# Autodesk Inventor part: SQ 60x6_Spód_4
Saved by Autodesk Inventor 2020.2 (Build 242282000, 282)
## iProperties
Created: 2006-08
Part Number: SQ 60x6_Spód_4
Material: Ogólny
Document SubType Name: Modeling
Designer: F.Stasiak
Manufacturer: Standard
Standards Organization: Custom
Stock Number: DIN EN 10210-2 SQ 60x6
Density: 1 g/cm^3
Appearance: Domyślna
Manager: www.cadconsulting.pl
Company: Fabian Stasiak CAD Consulting
G_L: 1000,0 mm
G_W: 60,000 mm
G_H: 60,000 mm
AFG_Item: 60 x 60 x 6
Author: F.Stasiak
Subject: Zbiór ćwiczeń. Autodesk Inventor 2020. Kurs podstawowy
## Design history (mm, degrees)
sketch "AFG_Detailed"
  geometry: L1 (-12, 54)-(-48, 54); L2 (-54, 48)-(-54, 12); L3 (-48, 6)-(-12, 6); L4 (-6, 12)-(-6, 48); L5 (-12, 60)-(-48, 60); L6 (-60, 48)-(-60, 12); L7 (-48, 0)-(-12, 0); L8 (0, 12)-(0, 48); A1 r 6 centre (-12, 48) between (-6, 48) and (-12, 54); A2 r 12 centre (-12, 48) between (0, 48) and (-12, 60); A3 r 6 centre (-12, 12) between (-12, 6) and (-6, 12); A4 r 12 centre (-12, 12) between (-12, 0) and (0, 12); A5 r 12 centre (-48, 12) between (-60, 12) and (-48, 0); A6 r 6 centre (-48, 12) between (-54, 12) and (-48, 6); A7 r 6 centre (-48, 48) between (-48, 54) and (-54, 48); A8 r 12 centre (-48, 48) between (-48, 60) and (-60, 48); 4 further points
  constraints: 16 end point, 16 point on circle, 16 tangent, 8 centre point, 6 point on line, 4 parallel, 2 perpendicular, 1 vertical
  dimensions: "d15" = 60 distance of point (-60, 0) point (0, 0) (= GEO_B); "d16" = 6 distance between parallel lines of L7 L3 (= GEO_S); "d17" = 6 distance between parallel lines of L8 L4 (= GEO_S); "d18" = 6 distance between parallel lines of L5 L1 (= GEO_S); "d19" = 6 distance between parallel lines of L6 L2 (= GEO_S); "d20" = 30 distance from line of point (-30, 30) L7 (= 0.5 x GEO_H); "d30" = 6 radius of A1 (= GEO_R1 - GEO_S); "GEO_R1" = 12 radius of A2; "d32" = 6 radius of A3 (= GEO_R1 - GEO_S); "d33" = 12 radius of A4 (= GEO_R1); "d34" = 12 radius of A5 (= GEO_R1); "d35" = 6 radius of A6 (= GEO_R1 - GEO_S); "d36" = 6 radius of A7 (= GEO_R1 - GEO_S); "d37" = 12 radius of A8 (= GEO_R1); "d38" = 30 distance from line of L6 point (-30, 30) (= 0.5 x GEO_B); "d39" = 60 distance between parallel lines of L7 L5 (= GEO_H)
sketch "AFG_Medium"
  geometry: L1 (-6, 54)-(-54, 54); L2 (-54, 54)-(-54, 6); L3 (-54, 6)-(-6, 6); L4 (-6, 6)-(-6, 54); L5 (0, 60)-(-60, 60); L6 (-60, 60)-(-60, 0); L7 (-60, 0)-(0, 0); L8 (0, 0)-(0, 60); 1 further point
  constraints: 16 end point, 4 parallel, 2 perpendicular, 1 vertical
  dimensions: "GEO_B" = 60 distance of L6.end L7.end; "GEO_S" = 6 distance between parallel lines of L7 L3; "d5" = 6 distance between parallel lines of L8 L4 (= GEO_S); "d6" = 6 distance between parallel lines of L5 L1 (= GEO_S); "d7" = 6 distance between parallel lines of L6 L2 (= GEO_S); "d12" = 30 distance from line of point (-30, 30) L7 (= 0.5 x GEO_H); "d40" = 60 distance between parallel lines of L7 L5 (= GEO_H); "d41" = 30 distance from line of L6 point (-30, 30) (= 0.5 x GEO_B)
sketch "AFG_Simplified"
  geometry: L1 (0, 60)-(-60, 60); L2 (-60, 60)-(-60, 0); L3 (-60, 0)-(0, 0); L4 (0, 0)-(0, 60); 1 further point
  constraints: 8 end point, 2 parallel, 1 perpendicular, 1 vertical
  dimensions: "d23" = 60 distance of L2.end L3.end (= GEO_B); "d28" = 30 distance from line of point (-30, 30) L3 (= 0.5 x GEO_H); "d42" = 60 distance between parallel lines of L3 L1 (= GEO_H); "d43" = 30 distance from line of point (-30, 30) L2 (= 0.5 x GEO_B)
derived "Szkielet podstawy.ipt"
  sketch "Szkic1"
    geometry: L1 (0, 0)-(1500, 0) reference; L2 (1500, 0)-(1500, 1000) reference; L3 (1500, 1000)-(0, 1000) reference; L4 (0, 1000)-(0, 0) reference
  sketch "Szkic2"
    geometry: L1 (0, 1000)-(0, 0) reference; L2 (0, 0)-(1500, 0) reference; L3 (1500, 0)-(1500, 1000) reference; L4 (500, 1000)-(1500, 1000) reference; L5 (1500, 1000)-(1500, 0) reference; L6 (1500, 0)-(500, 0) reference; L7 (500, 0)-(500, 1000) reference; L8 (1500, 1000)-(0, 1000) reference
node "AFG_StartWorkPoint_SQ 60x6_Spód_4"
node "AFG_EndWorkPoint_SQ 60x6_Spód_4"
node "AFG_HelpAxis"
node "AFG_HelpStart"
node "AFG_HelpEnd"
node "AFG_Midplane"
  node "AFG_Startplane"
  node "AFG_EndPlane"
node "AFG_Profile_AxisX_for_External_Matrix"
extrude "AFG_Detailed_SQ 60x6_Spód_4" join sketch "AFG_Detailed" stored distance "d49" = 0.13; taper "d50" = 0 deg
extrude "AFG_Simplified_SQ 60x6_Spód_4" join sketch "AFG_Simplified" stored distance "d51" = 0.13; taper "d52" = 0 deg
node "AFG_StartWorkPoint_SQ 60x6_Spód_3"
node "AFG_EndWorkPoint_SQ 60x6_Spód_3"
node "AFG_STARTCUTPLANE_SQ 60x6_Spód_4"
node "AFG_StartWorkPoint_SQ 60x6_Spód_1"
node "AFG_EndWorkPoint_SQ 60x6_Spód_1"
node "AFG_ENDCUTPLANE_SQ 60x6_Spód_4"
node "Bryła1"
node "Korpusy bryłowe"
node "Korpusy powierzchniowe"
other parameters: "GEO_H" = 60, "AFG_Origin_X" = 0 (= 0 x GEO_B) [user parameter], "AFG_Origin_Y" = 0 (= 0 x GEO_H) [user parameter], "AFG_IP_X2" = 0 (= 0 x GEO_B) [user parameter], "AFG_IP_Y4" = 0 (= 0 x GEO_H) [user parameter], "AFG_IP_X6" = 0 (= 0 x GEO_B) [user parameter], "AFG_IP_Y8" = 0 (= 0 x GEO_H) [user parameter], "d47" = 0, "d48" = 0, "G_L" = 1000 [user parameter], "d55" = 0, "d58" = 0
